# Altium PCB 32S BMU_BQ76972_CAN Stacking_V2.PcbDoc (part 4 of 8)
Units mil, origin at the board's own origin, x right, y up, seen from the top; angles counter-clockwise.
Board outline 7319.29 x 5216.54 mil, 4 copper layers (Top Layer, Layer 1, Layer 2, Bottom Layer), stack 73.068 mil thick; 811 components, 524 nets, 2320 pads, 2669 vias.
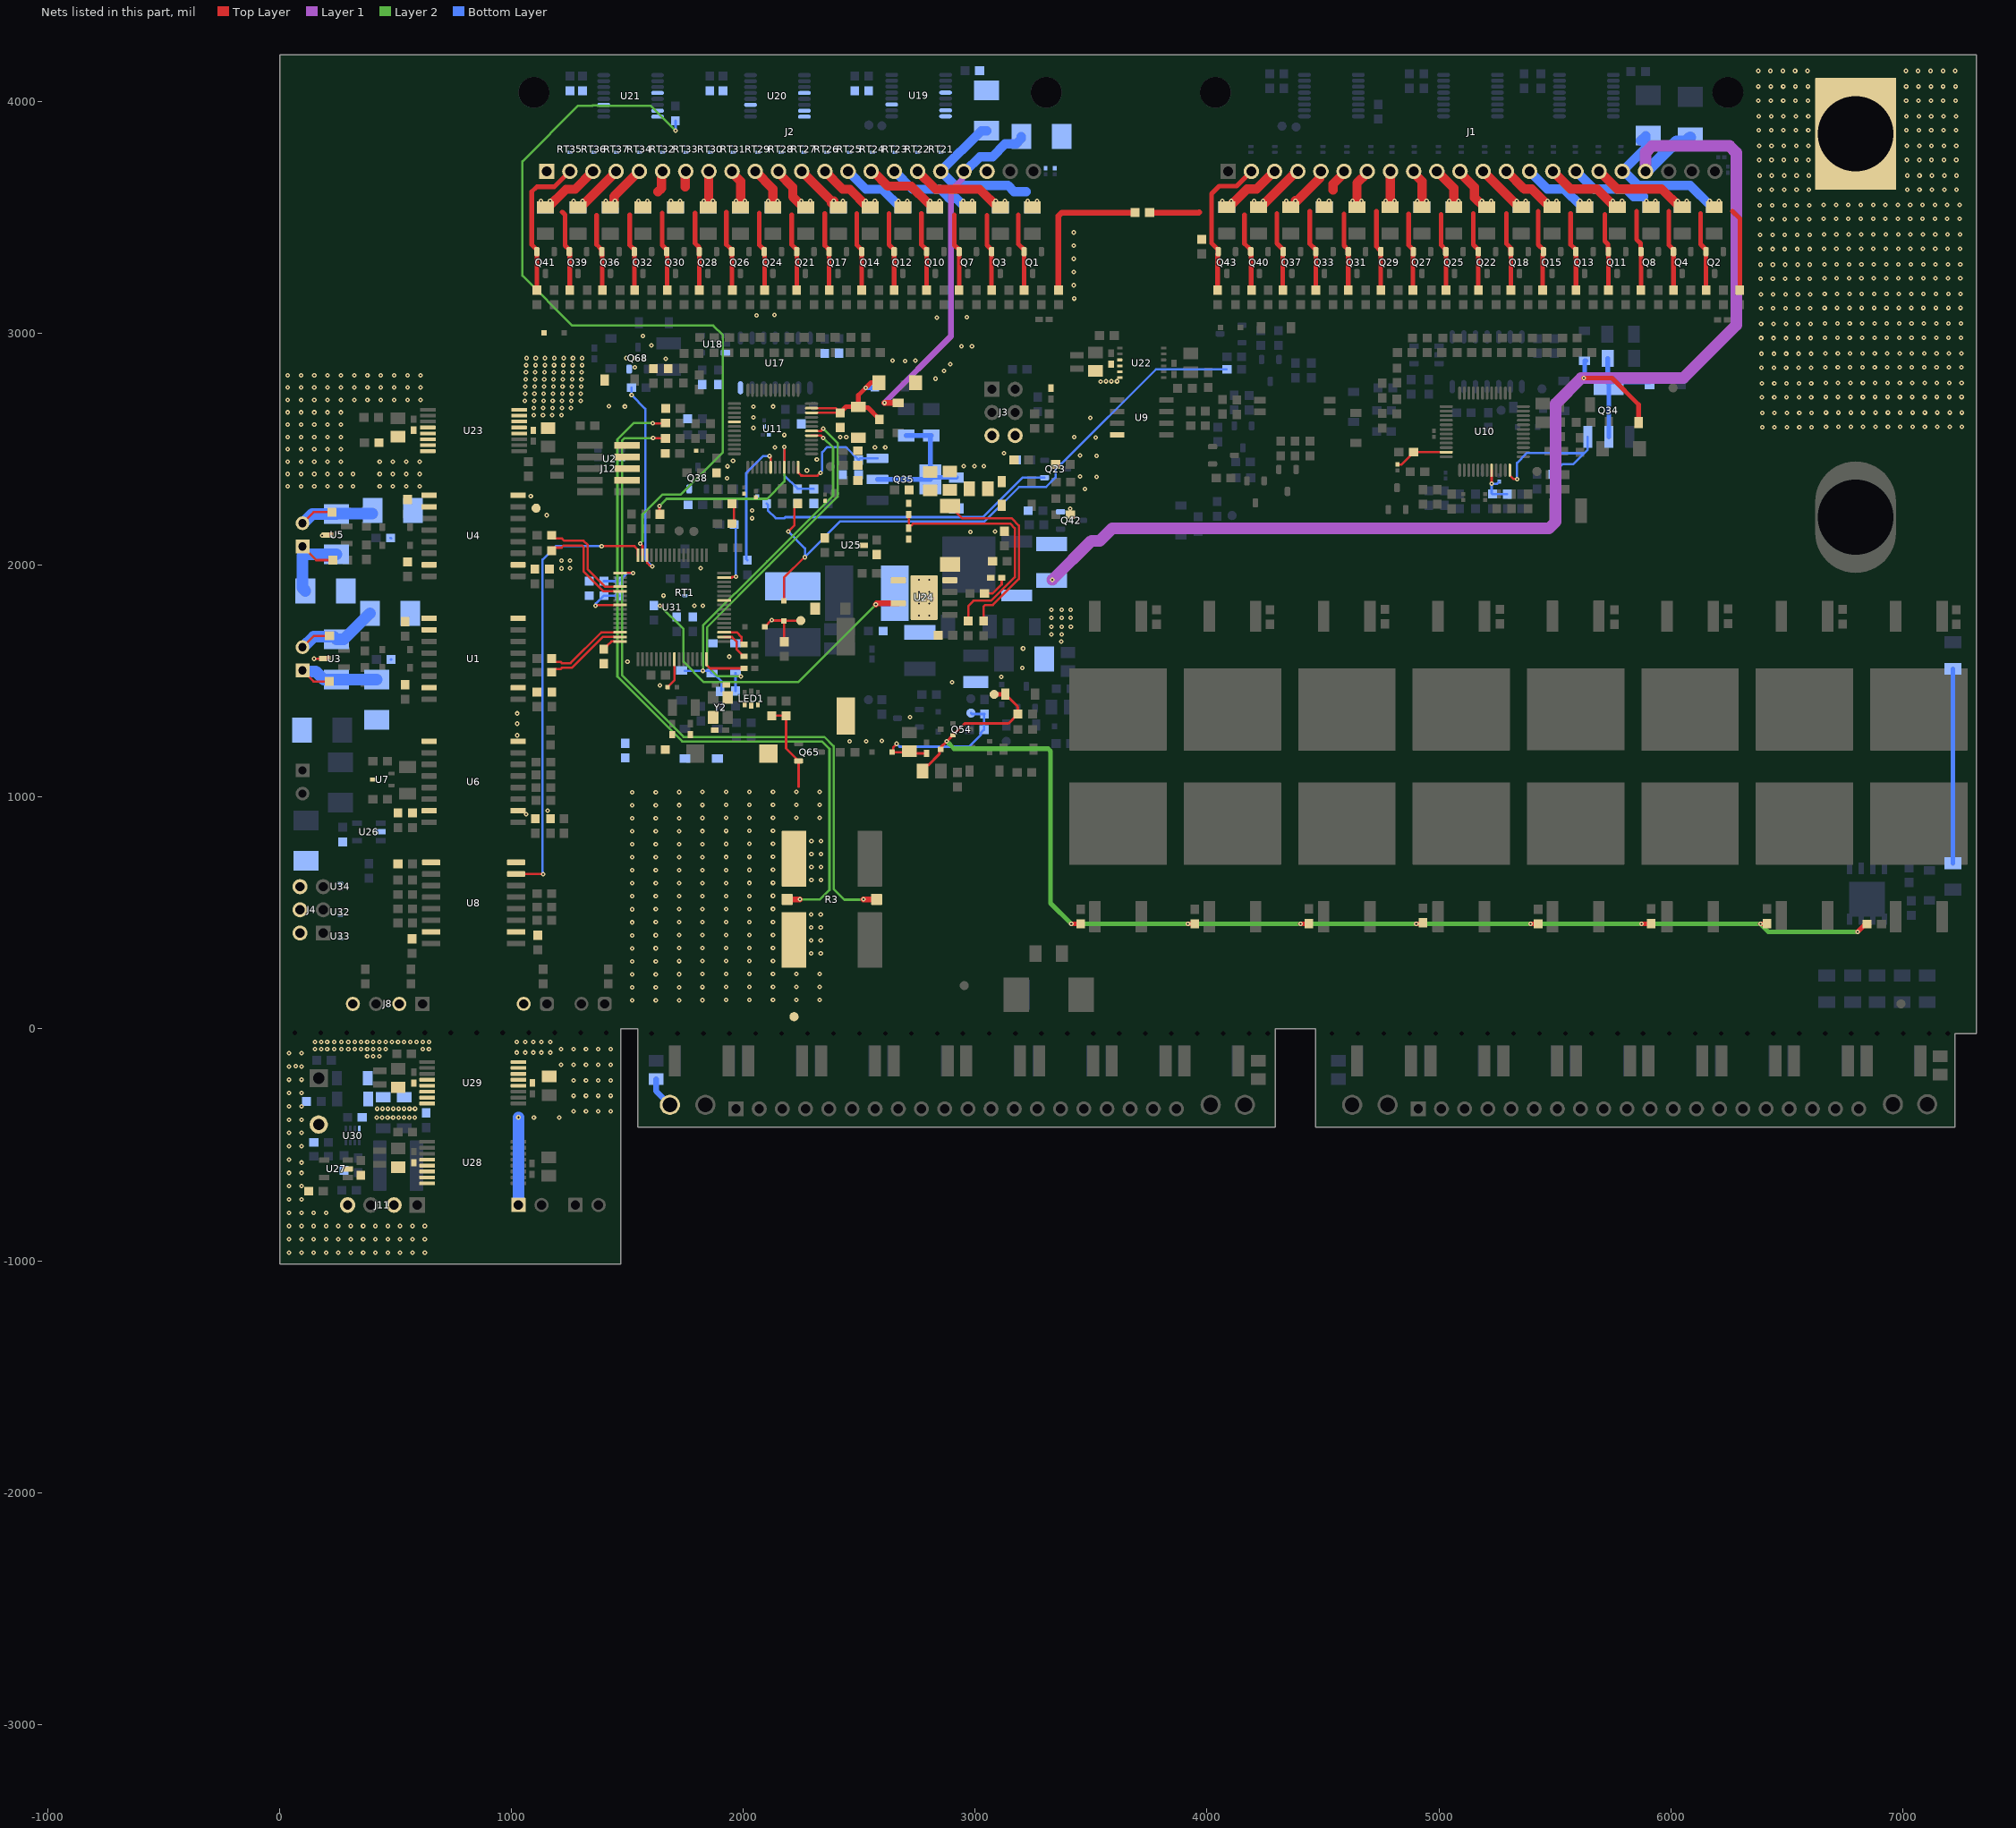
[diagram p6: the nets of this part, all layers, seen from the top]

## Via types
v1: diameter 19.68, hole 7.87, Top Layer to Bottom Layer, tented both sides, 2668 vias
v2: diameter 40, hole 20, Top Layer to Bottom Layer, 1 vias

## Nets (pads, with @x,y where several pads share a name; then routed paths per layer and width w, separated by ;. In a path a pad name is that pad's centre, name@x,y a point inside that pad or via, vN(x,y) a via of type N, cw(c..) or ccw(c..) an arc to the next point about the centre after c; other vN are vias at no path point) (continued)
BAT+: F1.1
  other v1: 6394.6,2596.17 6447.9,2596.17 6501.2,2596.17 6554.5,2596.17 6607.8,2596.17 6670.09,2597.79 6723.39,2597.79 6776.69,2597.79 6829.99,2597.79 6883.29,2597.79 6936.59,2597.79 6989.89,2597.79 7043.19,2597.79 7096.49,2597.79 7149.79,2597.79 7203.09,2597.79 7256.39,2597.79 6394.6,2656.71 6447.9,2656.71 6501.2,2656.71 6554.5,2656.71 6607.8,2656.71 6670.09,2658.33 6723.39,2658.33 6776.69,2658.33 6829.99,2658.33 6883.29,2658.33 6936.59,2658.33 6989.89,2658.33 7043.19,2658.33 7096.49,2658.33 7149.79,2658.33 7203.09,2658.33 7256.39,2658.33 6393.13,2724.21 6446.43,2724.21 6499.73,2724.21 6553.03,2724.21 6606.33,2724.21 6668.62,2725.83 6721.92,2725.83 6775.22,2725.83 6828.52,2725.83 6881.82,2725.83 6935.12,2725.83 6988.42,2725.83 7041.72,2725.83 7095.02,2725.83 7148.32,2725.83 7201.62,2725.83 7254.92,2725.83 6393.13,2784.75 6446.43,2784.75 6499.73,2784.75 6553.03,2784.75 6606.33,2784.75 6668.62,2786.37 6721.92,2786.37 6775.22,2786.37 6828.52,2786.37 6881.82,2786.37 6935.12,2786.37 6988.42,2786.37 7041.72,2786.37 7095.02,2786.37 7148.32,2786.37 7201.62,2786.37 7254.92,2786.37 6391.67,2852.25 6444.97,2852.25 6498.27,2852.25 6551.57,2852.25 6604.87,2852.25 6667.16,2853.87 6720.46,2853.87 6773.76,2853.87 6827.06,2853.87 6880.36,2853.87 6933.66,2853.87 6986.96,2853.87 7040.26,2853.87 7093.56,2853.87 7146.86,2853.87 7200.16,2853.87 7253.46,2853.87 6391.67,2912.79 6444.97,2912.79 6498.27,2912.79 6551.57,2912.79 6604.87,2912.79 6667.16,2914.41 6720.46,2914.41 6773.76,2914.41 6827.06,2914.41 6880.36,2914.41 6933.66,2914.41 6986.96,2914.41 7040.26,2914.41 7093.56,2914.41 7146.86,2914.41 7200.16,2914.41 7253.46,2914.41 6390.2,2980.3 6443.51,2980.3 6496.81,2980.3 6550.11,2980.3 6603.41,2980.3 6665.7,2981.91 6719,2981.91 6772.3,2981.91 6825.6,2981.91 6878.9,2981.91 6932.2,2981.91 6985.5,2981.91 7038.8,2981.91 7092.1,2981.91 7145.4,2981.91 7198.7,2981.91 7252,2981.91 6390.2,3040.83 6443.51,3040.83 6496.81,3040.83 6550.11,3040.83 6603.41,3040.83 6665.7,3042.45 6719,3042.45 6772.3,3042.45 6825.6,3042.45 6878.9,3042.45 6932.2,3042.45 6985.5,3042.45 7038.8,3042.45 7092.1,3042.45 7145.4,3042.45 7198.7,3042.45 7252,3042.45 6388.74,3108.34 6442.04,3108.34 6495.34,3108.34 6548.64,3108.34 6601.94,3108.34 6664.23,3109.95 6717.53,3109.95 6770.83,3109.95 6824.13,3109.95 6877.43,3109.95 6930.73,3109.95 6984.03,3109.95 7037.33,3109.95 7090.63,3109.95 7143.93,3109.95 7197.23,3109.95 7250.53,3109.95 6388.74,3168.88 6442.04,3168.88 6495.34,3168.88 6548.64,3168.88 6601.94,3168.88 6664.23,3170.49 6717.53,3170.49 6770.83,3170.49 6824.13,3170.49 6877.43,3170.49 6930.73,3170.49 6984.03,3170.49 7037.33,3170.49 7090.63,3170.49 7143.93,3170.49 7197.23,3170.49 7250.53,3170.49 6387.28,3236.38 6440.58,3236.38 6493.88,3236.38 6547.18,3236.38 6600.48,3236.38 6662.77,3237.99 6716.07,3237.99 6769.37,3237.99 6822.67,3237.99 6875.97,3237.99 6929.27,3237.99 6982.57,3237.99 7035.87,3237.99 7089.17,3237.99 7142.47,3237.99 7195.77,3237.99 7249.07,3237.99 6387.28,3296.92 6440.58,3296.92 6493.88,3296.92 6547.18,3296.92 6600.48,3296.92 6662.77,3298.53 6716.07,3298.53 6769.37,3298.53 6822.67,3298.53 6875.97,3298.53 6929.27,3298.53 6982.57,3298.53 7035.87,3298.53 7089.17,3298.53 7142.47,3298.53 7195.77,3298.53 7249.07,3298.53 6385.81,3364.42 6439.11,3364.42 6492.41,3364.42 6545.71,3364.42 6599.01,3364.42 6661.31,3366.03 6714.61,3366.03 6767.91,3366.03 6821.21,3366.03 6874.51,3366.03 6927.81,3366.03 6981.11,3366.03 7034.41,3366.03 7087.71,3366.03 7141.01,3366.03 7194.31,3366.03 7247.61,3366.03 6385.81,3424.96 6439.11,3424.96 6492.41,3424.96 6545.71,3424.96 6599.01,3424.96 6661.31,3426.57 6714.61,3426.57 6767.91,3426.57 6821.21,3426.57 6874.51,3426.57 6927.81,3426.57 6981.11,3426.57 7034.41,3426.57 7087.71,3426.57 7141.01,3426.57 7194.31,3426.57 7247.61,3426.57 6384.35,3492.46 6437.65,3492.46 6490.95,3492.46 6544.25,3492.46 6597.55,3492.46 6659.84,3494.07 6713.14,3494.07 6766.44,3494.07 6819.74,3494.07 6873.04,3494.07 6926.34,3494.07 6979.64,3494.07 7032.94,3494.07 7086.24,3494.07 7139.54,3494.07 7192.84,3494.07 7246.14,3494.07 6384.35,3553 6437.65,3553 6490.95,3553 6544.25,3553 6597.55,3553 6659.84,3554.61 6713.14,3554.61 6766.44,3554.61 6819.74,3554.61 6873.04,3554.61 6926.34,3554.61 6979.64,3554.61 7032.94,3554.61 7086.24,3554.61 7139.54,3554.61 7192.84,3554.61 7246.14,3554.61 6382.89,3620.5 6436.19,3620.5 6489.49,3620.5 6542.79,3620.5 6596.09,3620.5 7020.03,3620.5 7073.33,3620.5 7126.63,3620.5 7179.93,3620.5 7233.23,3620.5 6382.89,3681.04 6436.19,3681.04 6489.49,3681.04 6542.79,3681.04 6596.09,3681.04 7020.03,3681.04 7073.33,3681.04 7126.63,3681.04 7179.93,3681.04 7233.23,3681.04 6381.42,3748.54 6434.72,3748.54 6488.02,3748.54 6541.32,3748.54 6594.62,3748.54 7018.56,3748.54 7071.86,3748.54 7125.16,3748.54 7178.46,3748.54 7231.76,3748.54 6381.42,3809.08 6434.72,3809.08 6488.02,3809.08 6541.32,3809.08 6594.62,3809.08 7018.56,3809.08 7071.86,3809.08 7125.16,3809.08 7178.46,3809.08 7231.76,3809.08 6379.96,3876.58 6433.26,3876.58 6486.56,3876.58 6539.86,3876.58 6593.16,3876.58 7017.1,3876.58 7070.4,3876.58 7123.7,3876.58 7177,3876.58 7230.3,3876.58 6379.96,3937.12 6433.26,3937.12 6486.56,3937.12 6539.86,3937.12 6593.16,3937.12 7017.1,3937.12 7070.4,3937.12 7123.7,3937.12 7177,3937.12 7230.3,3937.12 6378.5,4004.62 6431.8,4004.62 6485.1,4004.62 6538.4,4004.62 6591.7,4004.62 7015.64,4004.62 7068.94,4004.62 7122.24,4004.62 7175.54,4004.62 7228.84,4004.62 6378.5,4065.16 6431.8,4065.16 6485.1,4065.16 6538.4,4065.16 6591.7,4065.16 7015.64,4065.16 7068.94,4065.16 7122.24,4065.16 7175.54,4065.16 7228.84,4065.16 6377.03,4132.66 6430.33,4132.66 6483.63,4132.66 6536.93,4132.66 6590.23,4132.66 7014.17,4132.66 7067.47,4132.66 7120.77,4132.66 7174.07,4132.66 7227.37,4132.66
BAT_IN: D10.2 C116.1 D2.2 D43.2 J1.19 R308.1 | length 5641.8
  Top Layer w20: v1(5624.52,2807.47) 5747.27,2807.47 5861.9,2692.85 D10.2@5861.9,2615.29
  Layer 1 w50: v1(3332.48,1937.18) 3501.47,2106.16 3537.95,2106.16 3590.51,2158.73 5474.67,2158.73 5503.96,2188.02 5503.96,2697.09 5614.34,2807.47 v1(5624.52,2807.47) 6054.95,2807.47 6282.83,3035.35 6282.83,3779.79 6253.54,3809.08 5920.57,3809.08 5891.28,3779.79 J1.19@5891.28,3699.61
  Bottom Layer w20: v1(5624.52,2807.47) 5628.49,2811.44 D2.2@5628.49,2881.95 D2.2@5634.49,2881.95
  Bottom Layer w50: J1.19@5891.28,3699.61 5895.75,3699.61 6025.29,3829.14 6066.23,3829.14 D43.2@6083.73,3846.64
BOT_ALERT: R11.1 R227.2 | length 89
  Top Layer w10: R11.1@1951.09,2179.71 1958.92,2187.54 R227.2@1958.92,2265.5
BOT_BAT: C70.2 C76.2 D3.2 D42.1 R198.2 U11.46 U11.47 | length 663.1
  Top Layer w10: U11.46@2293.98,2657.93 C76.2@2417.03,2657.93 ; U11.47@2293.98,2677.61 2398.33,2677.61 C76.2@2417.72,2658.22
  Top Layer w20: C76.2@2417.72,2657.24 2417.72,2658.22 2443.2,2683.71 C70.2@2496.13,2683.71 ; D42.1@2584.56,2787.97 2550.44,2787.97 2496.13,2733.67 C70.2@2496.13,2683.71 ; R198.2@2586.94,2629.57 2586.94,2630.56 2536.99,2680.51 2499.33,2680.51 C70.2@2496.13,2683.71
  Bottom Layer w20: v1(2527.95,2764.85) 2558.08,2764.85 D3.2@2567.64,2774.41
BOT_BAT_IN: D6.2 D45.2 J2.19 | length 1523.3
  Top Layer w25: v1(2608.27,2700.79) D6.2@2667.32,2700.79
  Layer 1 w25: v1(2608.27,2700.79) 2894.7,2987.22 2894.7,3617.24 2943.49,3666.03 2943.49,3691.66 J2.19@2951.43,3699.61
  Bottom Layer w25: J2.19@2945.74,3705.3 J2.19@2951.43,3699.61
  Bottom Layer w40: J2.19@2951.43,3699.61 2957.55,3699.61 3020.44,3762.5 3074.28,3762.5 3129.55,3817.76 3176.55,3817.76 3199.05,3840.26 D45.2@3199.05,3849.61
BOT_CB: R190.1 U31.14 | length 869.7
  Top Layer w10: U31.14@1584.51,2043.51 1585.29,2042.73 1585.29,2009.74 1597.19,1997.84 1605.21,1997.84 v1(1607.07,1995.99)
  Bottom Layer w10: R190.1@1517.6,2766.49 v1(1517.6,2734.26) 1576.61,2675.25 1576.61,2104.46 1577.35,2103.72 1577.35,2084.8 1576.61,2084.06 1576.61,2026.44 v1(1607.07,1995.99)
BOT_DDSG: D1.1 D17.1 R293.1 TP13.1 | length 255.2
  Top Layer w10: D17.1@2092.79,1734.91 2121.18,1763.3 v1(2122.12,1763.3) 2123.6,1761.82 D1.1@2169.28,1761.82 ; R293.1@2176.72,1669.96 2175.2,1671.49 D1.1@2175.2,1760.33 2246.14,1760.33 TP13.1@2247.37,1761.57
  Bottom Layer w10: v1@2120.26,1761.45 v1(2122.12,1763.3)
BOT_INH: R295.1 U31.15 | length 3459.2
  Top Layer w10: v1(1554.51,2094.26) 1564.82,2083.93 U31.15@1564.82,2043.51
  Layer 2 w10: v1(1554.51,2094.26) 1554.51,2094.51 1564.96,2104.96 1564.96,2219.8 1650.01,2304.85 1728.21,2304.85 1911.63,2488.27 1911.63,2992.26 1869.86,3034.04 1261.64,3034.04 1046.8,3248.87 1046.8,3742.12 1287.41,3982.73 1349.84,3982.73 1350.58,3983.47 1369.51,3983.47 1370.25,3982.73 1599.16,3982.73 v1(1706.98,3874.91)
  Bottom Layer w12: v1(1706.98,3874.91) R295.1@1706.98,3917.91
BOT_LD: D19.1 D35.2 R302.1 U11.41 | length 1528.3
  Top Layer w10: U11.41@2293.98,2559.5 2334.84,2559.5 2344.49,2549.85 v1(2345.17,2549.85)
  Layer 2 w10: v1(1825.8,1544.78) 1825.68,1544.91 1825.68,1739.74 2102.39,2016.45 2387.07,2301.13 2387.07,2507.95 v1(2345.17,2549.85)
  Bottom Layer w10: D35.2@1748.2,1544.78 v1(1825.8,1544.78) 1854.22,1544.78 D19.1@1864.34,1534.65 1870.35,1534.65 1905.58,1499.42 R302.1@1905.58,1457.5
BOT_PACK: D20.1 R299.1 U11.42 | length 1578.7
  Top Layer w10: U11.42@2293.98,2579.19 2334.84,2579.19 2344.68,2589.03 v1(2345.17,2589.03)
  Layer 2 w10: v1(1989.59,1520.84) 1889.38,1520.84 1843.68,1566.54 1843.68,1732.28 2109.85,1998.45 2406.99,2295.59 2406.99,2527.22 v1(2345.17,2589.03)
  Bottom Layer w10: R299.1@1966.1,1457.5 D20.1@1966.1,1534.65
BOT_SHUT: C84.1 R15.1 R252.2 U11.33 | length 1129.3
  Top Layer w10: v1(1637.97,2256.18) 1637.97,2222.81 R15.1@1640.28,2220.5 ; U11.33@2176.85,2422.69 v1@2176.85,2509.85
  Layer 2 w10: v1(1637.97,2256.18) 1668.6,2286.8 2102.41,2286.8 2176.85,2361.24 v1(2176.85,2510.13)
  Bottom Layer w10: v1(2176.85,2510.13) 2176.85,2387.3 2233.63,2330.52 R252.2@2233.63,2329.54 C84.1@2303.73,2329.54
BOT_WAKE: R254.1 U31.63 | length 279.9
  Top Layer w10: U31.63@1917.19,1947.05 1950.18,1947.05 1953.35,1950.23 v1(1967.62,1950.23)
  Bottom Layer w10: R254.1@1960.33,2175.36 1967.62,2168.07 v1(1967.62,1950.23)
BOTAFE_DCHG: Q23.1 R223.2 | length 1311
  Bottom Layer w10: R223.2@2100.42,2265.88 2105.67,2260.63 2105.67,2237.06 2139.59,2203.14 2176.47,2203.14 2180.82,2207.5 3033.14,2207.5 3203.6,2377.95 Q23.1@3299.21,2377.95
BOTAFE_DDSG: D1.2 R222.2 R246.1 | length 2681.6
  Top Layer w10: D1.2@2175.2,1846.95 2175.2,1946.14 2263.89,2034.84 v1(2265.6,2034.84) ; v1(2193.54,2145.41) 2220.49,2172.35 2220.49,2252.84 R222.2@2234.19,2266.55
  Bottom Layer w10: v1(2193.54,2145.41) 2265.6,2073.35 v1(2265.6,2034.84) 2265.6,2036.54 2418.55,2189.5 3040.6,2189.5 3188.95,2337.85 3305.53,2337.85 3346.46,2378.78 3346.46,2414.53 3372.09,2440.17 3374.17,2440.17 3779.4,2845.39 R246.1@4084.81,2845.39
BOTGND_Sim: R365.2 TP28.1 | length 134.8
  Bottom Layer w25: R365.2@1624.02,-217.03 1624.02,-268.3 TP28.1@1683.07,-327.35
BOTHOFF: R18.1 U11.30 | length 559.7
  Top Layer w10: v1(2112.97,2471.17) 2112.97,2468.55 2117.45,2464.07 2117.45,2423.04 U11.30@2117.79,2422.69
  Bottom Layer w10: R18.1@2017.58,2021.75 2012.43,2026.9 2012.43,2397.95 2085.66,2471.17 v1(2112.97,2471.17)
CAN0_RXD: R7.1 U31.31 | length 358.3
  Top Layer w10: R7.1@1173.34,1538.44 1187.04,1552.14 1210.97,1552.14 1216.96,1558.12 1260.68,1558.12 1393.7,1691.15 U31.31@1468.37,1691.15
CAN0_TXD: R6.1 U31.30 | length 358.3
  Top Layer w10: R6.1@1173.34,1597.49 1187.04,1583.79 1210.97,1583.79 1216.96,1577.81 1254.91,1577.81 1386.25,1709.15 1386.43,1709.15 1388.11,1710.83 U31.30@1468.37,1710.83
CAN0H: D51.1 D53.2 L3.2 P3.1 | length 472.6
  Top Layer w10: P3.1@98.53,1546.71 146.17,1499.07 L3.2@214.21,1499.07
  Bottom Layer w50: P3.1@98.53,1546.71 103.06,1542.18 155.12,1542.18 190.75,1506.55 D51.1@244.74,1506.55 418.74,1506.55 D53.2@419.01,1506.82
CAN0L: D51.2 D56.2 L4.2 P3.2 | length 496.6
  Top Layer w10: P3.2@98.53,1646.71 147.75,1695.92 L4.2@214.68,1695.92
  Bottom Layer w50: P3.2@98.53,1646.71 100.98,1646.71 146.18,1691.91 233.4,1691.91 D51.2@244.74,1680.56 276.64,1680.56 D56.2@388.72,1792.65
CAN1_RXD: R16.1 U31.21 | length 439.8
  Top Layer w10: R16.1@1175.94,2075.76 1176.4,2076.22 1215.77,2076.22 1225.16,2085.61 1305.01,2085.61 1310.87,2079.75 1310.87,1974.88 1397.75,1888 U31.21@1468.37,1888
CAN1_TXD: R14.1 U31.20 | length 443.9
  Top Layer w10: R14.1@1175.94,2124.98 1185.63,2115.29 1217.54,2115.29 1226.93,2105.9 1310.17,2105.9 1328.87,2087.2 1328.87,1982.34 1403.52,1907.68 U31.20@1468.37,1907.68
CAN1H: D50.1 D54.2 L6.2 P2.1 | length 461.3
  Top Layer w10: P2.1@98.53,2081.46 157.59,2022.4 L6.2@229.46,2022.4
  Bottom Layer w50: D54.2@110.69,1889.76 98.53,1901.92 98.53,2041.93 104.46,2047.86 D50.1@244.74,2047.86
CAN1L: D50.2 D57.2 L7.2 P2.2 | length 466
  Top Layer w10: P2.2@98.53,2181.46 146.17,2229.09 L7.2@226.02,2229.09
  Bottom Layer w50: P2.2@98.53,2181.46 100.98,2181.46 141.4,2221.87 D50.2@244.74,2221.87 246.27,2223.4 D57.2@399.96,2223.4
Cell0: J2.2 Q41.2 R185.1 | length 634.6
  Top Layer w20: R185.1@1109.14,3186.81 Q41.2@1109.14,3353.15 1107.33,3354.96 1107.33,3362.83 1087.02,3383.15 1087.02,3611.3 1108.8,3633.09 1184.91,3633.09 J2.2@1251.43,3699.61
Cell1: J2.3 Q39.2 R149.1 R151.1 R181.1 | length 621.7
  Top Layer w20: 1216.81,3523.62 1219.11,3523.62 1230.83,3511.91 1230.83,3379.45 1249.25,3361.02 Q39.2@1249.25,3353.15 1249.25,3345.28 1251.22,3343.31 R181.1@1251.22,3186.81
  Top Layer w40: R149.1@1146.54,3544.09 1157.37,3544.09 1235.38,3622.11 1273.93,3622.11 J2.3@1351.43,3699.61
  other v1: 1126.86,3571.65 1166.23,3571.65
Cell2: J2.4 Q36.2 R144.1 R146.1 R177.1 | length 563.2
  Top Layer w20: 1366.68,3509.55 1366.68,3383.7 1387.55,3362.83 1387.55,3354.96 1390.53,3351.98 1390.53,3187.98 R177.1@1391.7,3186.81
  Top Layer w40: R144.1@1286.65,3544.09 1297.48,3544.09 1451.43,3698.05 J2.4@1451.43,3699.61
  other v1: 1266.97,3571.65 1306.34,3571.65
Cell3: J2.5 Q32.2 R140.1 R142.1 R173.1 | length 547.7
  Top Layer w20: 1510.06,3511.91 1510.06,3380.43 1529.47,3361.02 Q32.2@1529.47,3353.15 1530.45,3352.17 1530.45,3187.79 R173.1@1531.44,3186.81
  Top Layer w40: R140.1@1426.48,3544.09 1437.18,3544.09 1442.77,3549.69 1442.77,3591.34 1551.04,3699.61 J2.5@1551.43,3699.61
  other v1: 1406.79,3571.65 1446.16,3571.65
Cell4: J2.6 Q30.2 R136.1 R138.1 R169.1 | length 438.9
  Top Layer w20: 1649.85,3519.71 1649.85,3380.75 1669.58,3361.02 Q30.2@1669.58,3353.15 1669.58,3345.28 1671.54,3343.31 R169.1@1671.54,3186.81
  Top Layer w40: 1631.34,3610.91 1646.36,3625.92 1646.36,3694.53 J2.6@1651.43,3699.61
  other v1: 1547.18,3571.65 1586.55,3571.65
Cell5: J2.7 Q28.2 R132.1 R134.1 R165.1 | length 415.3
  Top Layer w20: 1791.75,3520.22 1791.75,3388.78 1807.87,3372.66 1807.87,3354.96 Q28.2@1809.68,3353.15 R165.1@1809.68,3186.81
  Top Layer w40: 1749.7,3633.09 1749.7,3697.87 J2.7@1751.43,3699.61 J2.7@1751.43,3692.43
  other v1: 1687.29,3571.65 1726.66,3571.65
Cell6: J2.8 Q26.2 R128.1 R130.1 R161.1 | length 503.9
  Top Layer w20: 1926.9,3523.62 1926.9,3383.92 1949.79,3361.02 Q26.2@1949.79,3353.15 1951.08,3351.86 1951.08,3188.1 R161.1@1952.37,3186.81
  Top Layer w40: R128.1@1849.05,3544.09 1850.24,3545.28 1850.24,3698.42 J2.8@1851.43,3699.61
  other v1: 1829.37,3571.65 1868.74,3571.65
Cell7: J2.9 Q24.2 R124.1 R126.1 R157.1 | length 512.9
  Top Layer w20: 2069.01,3519.71 2069.01,3381.91 2089.9,3361.02 Q24.2@2089.9,3353.15 2089.9,3345.28 2091.87,3343.31 R157.1@2091.87,3186.81
  Top Layer w40: J2.9@1951.43,3699.61 1951.43,3692.43 1987.8,3656.06 R124.1@1987.8,3544.09
  other v1: 1968.11,3571.65 2007.48,3571.65
Cell8: J2.10 Q21.2 R119.1 R120.1 R122.1 | length 521.1
  Top Layer w20: 2208.21,3511.91 2208.21,3382.82 2230.01,3361.02 Q21.2@2230.01,3353.15 R119.1@2230.01,3186.81
  Top Layer w40: J2.10@2051.43,3699.61 2127.3,3623.74 R120.1@2127.3,3544.09
  other v1: 2107.62,3571.65 2146.99,3571.65
Cell9: J2.11 Q17.2 R83.1 R85.1 R115.1 | length 548.4
  Top Layer w20: 2351.43,3516.73 2351.43,3379.71 2370.12,3361.02 Q17.2@2370.12,3353.15 R115.1@2370.12,3186.81
  Top Layer w40: J2.11@2151.43,3699.61 2151.43,3692.43 2213.08,3630.78 2213.08,3589.56 2258.55,3544.09 R83.1@2269.38,3544.09
  other v1: 2249.69,3571.65 2289.06,3571.65
Cell10: J2.12 Q14.2 R79.1 R81.1 R111.1 | length 568
  Top Layer w20: 2489.34,3518.23 2489.34,3381.91 2508.41,3362.83 2508.41,3354.96 Q14.2@2510.22,3353.15 R111.1@2510.22,3186.81
  Top Layer w40: J2.12@2251.43,3699.61 2379.39,3571.65 v1(2389.8,3571.65) ; R79.1@2380.45,3562.3 2398.66,3544.09 R79.1@2409.49,3544.09
  other v1: 2429.17,3571.65
Cell11: J2.13 Q12.2 R75.1 R77.1 R107.1 | length 599.7
  Top Layer w20: 2628.21,3516.73 2628.21,3383.15 2650.33,3361.02 Q12.2@2650.33,3353.15 R107.1@2650.33,3186.81
  Top Layer w40: J2.13@2351.43,3699.61 2428.93,3622.11 2458.8,3622.11 2536.81,3544.09 R75.1@2547.64,3544.09
  other v1: 2527.95,3571.65 2567.32,3571.65
Cell12: J2.14 Q10.2 R71.1 R73.1 R103.1 | length 650.9
  Top Layer w20: 2768.32,3516.73 2768.32,3383.15 2790.44,3361.02 Q10.2@2790.44,3353.15 R103.1@2790.44,3186.81
  Top Layer w30: R71.1@2677.14,3544.09 R71.1@2687.97,3544.09
  Bottom Layer w40: J2.14@2451.43,3699.61 2528.93,3622.11 2599.13,3622.11 2677.14,3544.09 R73.1@2687.97,3544.09
  other v1: 2668.28,3571.65 2707.65,3571.65
Cell13: J2.15 Q7.2 R68.1 R70.1 R99.1 | length 672.4
  Top Layer w20: 2910.16,3511.91 2910.16,3381.42 2930.55,3361.02 Q7.2@2930.55,3353.15 R99.1@2930.55,3186.81
  Top Layer w40: J2.15@2551.43,3699.61 2558.61,3699.61 2622.78,3635.44 2723.72,3635.44 2796.85,3562.3 2815.06,3544.09 R68.1@2825.89,3544.09
  other v1: 2806.2,3571.65 2845.57,3571.65
Cell14: J2.16 Q3.2 R63.1 R65.1 R95.1 | length 711.9
  Top Layer w20: 3050.81,3509.49 3050.81,3380.87 3070.66,3361.02 Q3.2@3070.66,3353.15 R95.1@3070.66,3186.81
  Bottom Layer w40: J2.16@2651.43,3699.61 2728.93,3622.11 2849.3,3622.11 2873.72,3597.69 2873.9,3597.69 2888.57,3583.01 2888.57,3582.83 2918.38,3582.83 2957.12,3544.09 R65.1@2967.95,3544.09
  other v1: 2948.26,3571.65 2987.63,3571.65
Cell15: J2.17 Q1.2 R59.1 R61.1 R91.1 | length 756.6
  Top Layer w20: 3186.11,3511.91 3186.11,3385.68 3210.76,3361.02 Q1.2@3210.76,3353.15 3211.02,3352.89 3211.02,3187.07 R91.1@3211.28,3186.81
  Top Layer w40: J2.17@2751.43,3699.61 2828.93,3622.11 3019.22,3622.11 3097.23,3544.09 R59.1@3108.06,3544.09
  other v1: 3088.37,3571.65 3127.74,3571.65
Cell16: D46.2 J2.18 R55.1 R57.1 R87.1 R152.1 | length 1342
  Top Layer w25: R87.1@3359.26,3186.81 3359.26,3507.01 3373.9,3521.66 R152.1@3688.98,3521.66
  Bottom Layer w40: D46.2@3049.1,3874.41 3026.24,3874.41 J2.18@2851.43,3699.61 2912.7,3638.34 3076.81,3638.34 3141.65,3638.34 3167.85,3612.13 3220.36,3612.13 ; R57.1@3235.89,3544.09 R57.1@3246.72,3544.09
  other v1: 3227.03,3571.65 3266.4,3571.65
Cell16B: J1.2 Q43.2 R152.2 R153.1 R186.1 | length 854.3
  Top Layer w20: R186.1@4045.79,3186.81 4045.79,3342.87 4048.2,3345.28 Q43.2@4048.2,3353.15 4046.39,3354.96 4046.39,3362.83 4019.76,3389.46 4019.76,3602.73 4052.47,3635.44 4127.11,3635.44 J1.2@4191.28,3699.61
  Top Layer w25: R152.2@3751.97,3521.66 3964.81,3521.66 3965.63,3522.48
Cell17: J1.3 Q40.2 R148.1 R150.1 R182.1 | length 607.8
  Top Layer w20: 4161.65,3511.91 4161.65,3387.83 4188.46,3361.02 Q40.2@4188.46,3353.15 4190.27,3351.34 4190.27,3188.68 R182.1@4192.14,3186.81
  Top Layer w40: R148.1@4085.18,3545.08 4096.01,3545.08 4173.53,3622.6 4214.27,3622.6 J1.3@4291.28,3699.61
  other v1: 4065.5,3572.64 4104.87,3572.64
Cell18: J1.4 Q37.2 R145.1 R147.1 R178.1 | length 575.2
  Top Layer w20: 4301.63,3516.73 4301.63,3388.12 4328.72,3361.02 Q37.2@4328.72,3353.15 4328.72,3345.28 4326.82,3343.38 R178.1@4326.82,3186.81
  Top Layer w40: R145.1@4222.01,3545.08 4232.83,3545.08 4387.36,3699.61 J1.4@4391.28,3699.61
  other v1: 4202.32,3572.64 4241.69,3572.64
Cell19: J1.5 Q33.2 R141.1 R143.1 R174.1 | length 547.1
  Top Layer w20: 4442.9,3527.56 4442.9,3387.1 4468.98,3361.02 Q33.2@4468.98,3353.15 R174.1@4468.98,3186.81
  Top Layer w40: R141.1@4361.64,3545.08 R141.1@4372.47,3545.08 ; v1(4381.33,3572.64) 4389.87,3572.64 4486.2,3668.97 4486.2,3694.53 J1.5@4491.28,3699.61 J1.5@4491.28,3692.43
  other v1: 4341.96,3572.64
Cell20: J1.6 Q31.2 R137.1 R139.1 R170.1 | length 437
  Top Layer w20: 4591.28,3516.24 4591.28,3378.99 4607.44,3362.83 4607.44,3354.96 Q31.2@4609.25,3353.15 R170.1@4609.25,3186.81
  Top Layer w40: 4543.79,3619.11 4543.79,3644.94 4591.28,3692.43 J1.6@4591.28,3699.61
  other v1: 4526.07,3572.64 4483.34,3573.46
Cell21: J1.7 Q29.2 R133.1 R135.1 R166.1 | length 599.8
  Top Layer w20: 4730.71,3527.56 4730.71,3374.55 4742.42,3362.83 4747.7,3362.83 4749.51,3361.02 R166.1@4749.51,3186.81
  Top Layer w40: R133.1@4646.65,3545.08 4646.65,3647.8 ; 4646.65,3572.64 4646.65,3647.8 ; J1.7@4691.28,3699.61 4691.28,3692.43 4646.65,3647.8
  other v1: 4626.96,3572.64 4666.33,3572.64
Cell22: J1.8 Q27.2 R129.1 R131.1 R162.1 | length 493.4
  Top Layer w20: 4869.99,3515.94 4869.99,3380.81 4887.96,3362.83 4887.96,3354.96 Q27.2@4889.77,3353.15 4889.77,3345.28 4887.68,3343.19 R162.1@4887.68,3186.81
  Top Layer w40: R129.1@4789.56,3545.08 4790.42,3545.94 4790.42,3698.75 J1.8@4791.28,3699.61
  other v1: 4769.88,3572.64 4809.25,3572.64
Cell23: J1.9 Q25.2 R125.1 R127.1 R158.1 | length 505.6
  Top Layer w20: 5009.04,3514.1 5009.04,3382.02 5028.22,3362.83 5028.22,3354.96 5030.28,3352.9 5030.28,3187.06 R158.1@5030.53,3186.81
  Top Layer w40: J1.9@4891.28,3699.61 4891.28,3692.43 4927.17,3656.53 R125.1@4927.17,3545.08
  other v1: 4907.49,3572.64 4946.86,3572.64
Cell24: J1.10 Q22.2 R121.1 R123.1 R154.1 | length 523.7
  Top Layer w20: 5148.8,3516.73 5148.8,3382.52 5170.3,3361.02 Q22.2@5170.3,3353.15 R154.1@5170.3,3186.81
  Top Layer w40: J1.10@4991.28,3699.61 5064.55,3626.34 R121.1@5064.55,3545.08
  other v1: 5044.86,3572.64 5084.23,3572.64
Cell25: J1.11 Q18.2 R84.1 R86.1 R116.1 | length 546.2
  Top Layer w20: 5291.28,3516.73 5291.28,3387.71 5308.75,3370.24 5308.75,3354.96 Q18.2@5310.56,3353.15 R116.1@5310.56,3186.81
  Top Layer w40: J1.11@5091.28,3699.61 5091.28,3692.43 5152.92,3630.78 5152.92,3587.06 5194.9,3545.08 R84.1@5205.73,3545.08
  other v1: 5186.04,3572.64 5225.41,3572.64
Cell26: J1.12 Q15.2 R80.1 R82.1 R112.1 | length 580
  Top Layer w20: 5428.71,3527.56 5428.71,3383.13 5450.82,3361.02 Q15.2@5450.82,3353.15 5450.82,3345.28 5447.66,3342.11 R112.1@5447.66,3186.81
  Top Layer w40: J1.12@5191.28,3699.61 5191.28,3698.24 5344.43,3545.08 R80.1@5355.26,3545.08
  other v1: 5335.58,3572.64 5374.95,3572.64
Cell27: J1.13 Q13.2 R76.1 R78.1 R108.1 | length 600.3
  Top Layer w20: 5568.28,3516.73 5568.28,3383.82 5591.08,3361.02 Q13.2@5591.08,3353.15 R108.1@5591.08,3186.81
  Top Layer w40: J1.13@5291.28,3699.61 5368.28,3622.6 5399.88,3622.6 5477.4,3545.08 R76.1@5488.22,3545.08
  other v1: 5468.54,3572.64 5507.91,3572.64
Cell28: J1.14 Q11.2 R72.1 R74.1 R104.1 | length 634.6
  Top Layer w20: 5716.05,3513.89 5716.05,3397.86 5729.54,3384.37 5729.54,3354.96 Q11.2@5731.35,3353.15 R104.1@5731.35,3186.81
  Bottom Layer w40: J1.14@5391.28,3699.61 5468.28,3622.6 5540.14,3622.6 5617.66,3545.08 R74.1@5628.49,3545.08
  other v1: 5608.8,3572.64 5648.17,3572.64
Cell29: J1.15 Q8.2 R67.1 R69.1 R100.1 | length 691.8
  Top Layer w20: 5852.76,3527.56 5852.76,3405.39 5869.8,3388.35 5869.8,3354.96 Q8.2@5871.61,3353.15 R100.1@5871.61,3186.81
  Top Layer w40: J1.15@5491.28,3699.61 5568.28,3622.6 5682.12,3622.6 5759.64,3545.08 R67.1@5770.47,3545.08
  other v1: 5750.78,3572.64 5790.15,3572.64
Cell30: J1.16 Q4.2 R64.1 R66.1 R96.1 | length 697.6
  Top Layer w20: 5991.28,3527.56 5991.28,3381.62 6011.87,3361.02 Q4.2@6011.87,3353.15 6012.19,3352.83 6012.19,3187.13 R96.1@6012.51,3186.81
  Bottom Layer w40: J1.16@5591.28,3699.61 5668.28,3622.6 5807.58,3622.6 5839.84,3590.34 5883.26,3590.34 ; R66.1@5903.88,3545.08 R66.1@5914.71,3545.08
  other v1: 5895.02,3572.64 5934.39,3572.64
Cell31: J1.17 Q2.2 R60.1 R62.1 R92.1 | length 761.9
  Top Layer w20: 6128.35,3516.73 6128.35,3384.81 6152.13,3361.02 Q2.2@6152.13,3353.15 6152.32,3352.96 6152.32,3187 R92.1@6152.51,3186.81
  Top Layer w40: J1.17@5691.28,3699.61 5768.28,3622.6 5960.93,3622.6 6038.45,3545.08 R60.1@6049.27,3545.08
  other v1: 6029.59,3572.64 6068.96,3572.64
Cell32: D44.2 J1.18 R56.1 R58.1 R88.1 | length 1042.5
  Top Layer w20: 6266.14,3527.56 6298.25,3495.45 R88.1@6298.25,3186.81
  Bottom Layer w40: D44.2@5869.88,3831.05 5892.38,3853.55 5892.38,3800.71 J1.18@5791.28,3699.61 5798.46,3699.61 5859.72,3638.34 6016.65,3638.34 6016.78,3638.46 6083.73,3638.46 6177.12,3545.08 R58.1@6187.94,3545.08
  other v1: 6168.26,3572.64 6207.63,3572.64
CSN: R3.4 R251.1 | length 3063.5
  Top Layer w10: v1(1610.27,2548.45) R251.1@1662.86,2548.45
  Top Layer w25: v1(2517.69,558.8) R3.4@2574.8,558.8
  Layer 2 w10: v1(1610.27,2548.45) 1487.22,2548.45 1476.38,2537.6 1476.38,1525.59 1742.13,1259.84 2349.25,1259.84 2389.47,1219.61 2389.47,604.11 2436.03,557.55 2516.44,557.55 v1(2517.69,558.8)
CSP: R3.3 R239.1 | length 3110.9
  Top Layer w10: v1(1609.07,2612.35) R239.1@1662.9,2612.35
  Top Layer w25: R3.3@2188.98,558.8 v1(2244.09,558.8)
  Layer 2 w10: v1(1609.07,2612.35) 1608.07,2613.35 1526.67,2613.35 1456.69,2543.37 1456.69,1519.82 1736.36,1240.16 2339.52,1240.16 2371.47,1208.2 2371.47,599.82 2330.45,558.8 v1(2244.09,558.8)
Current+: C137.2 D32.2 D33.2 Q65.2 R2.2 R3.1 R294.1 TP14.1 | length 390
  Top Layer w10: R294.1@2122.27,1351.24 C137.2@2184.22,1351.24 2184.22,1210.43 Q65.2@2238.2,1156.45 2238.2,1045.53
  other v1: 1520.68,123.39 1621.81,123.69 1722.95,123.98 1824.08,124.27 1925.21,124.56 2026.34,124.86 2127.47,125.15 2228.61,125.44 2329.74,125.73 1520.68,179.5 1621.81,179.79 1722.95,180.08 1824.08,180.38 1925.21,180.67 2026.34,180.96 2127.47,181.25 2228.61,181.55 2329.74,181.84 1520.68,235.6 1621.81,235.9 1722.95,236.19 1824.08,236.48 1925.21,236.77 2026.34,237.07 2127.47,237.36 2228.61,237.65 2329.74,237.95 1520.68,291.71 1621.81,292 1722.95,292.29 1824.08,292.59 1925.21,292.88 2026.34,293.17 2127.47,293.47 2292.59,325.43 2333.9,325.43 1520.68,347.81 1621.81,348.11 1722.95,348.4 1824.08,348.69 1925.21,348.99 2026.34,349.28 2127.47,349.57 2292.59,381.53 2333.9,381.53 1520.68,403.92 1621.81,404.21 1722.95,404.51 1824.08,404.8 1925.21,405.09 2026.34,405.38 2127.47,405.68 2292.59,437.64 2333.9,437.64 1520.68,460.03 1621.81,460.32 1722.95,460.61 1824.08,460.9 1925.21,461.2 2026.34,461.49 2127.47,461.78 2292.59,493.75 2333.9,493.75 1520.68,516.13 1621.81,516.42 1722.95,516.72 1824.08,517.01 1925.21,517.3 2026.34,517.59 2127.47,517.89 1520.68,572.24 1621.81,572.53 1722.95,572.82 1824.08,573.11 1925.21,573.41 2026.34,573.7 2127.47,573.99 1520.68,628.34 1621.81,628.63 1722.95,628.93 1824.08,629.22 1925.21,629.51 2026.34,629.81 2127.47,630.1 2293.31,642.05 2334.62,642.05 1520.68,684.45 1621.81,684.74 1722.95,685.03 1824.08,685.33 1925.21,685.62 2026.34,685.91 2127.47,686.2 2293.31,698.16 2334.62,698.16 1520.68,740.55 1621.81,740.85 1722.95,741.14 1824.08,741.43 1925.21,741.72 2026.34,742.02 2127.47,742.31 2293.31,754.26 2334.62,754.26 1520.68,796.66 1621.81,796.95 1722.95,797.24 1824.08,797.54 1925.21,797.83 2026.34,798.12 2127.47,798.41 2293.31,810.37 2334.62,810.37 1520.68,852.76 1621.81,853.06 1722.95,853.35 1824.08,853.64 1925.21,853.93 2026.34,854.23 2127.47,854.52 1520.68,908.87 1621.81,909.16 1722.95,909.45 1824.08,909.75 1925.21,910.04 2026.34,910.33 2127.47,910.63 2228.61,910.92 2329.74,911.21 1520.68,964.98 1621.81,965.27 1722.95,965.56 1824.08,965.85 1925.21,966.15 2026.34,966.44 2127.47,966.73 2228.61,967.02 2329.74,967.32 1520.68,1021.08 1621.81,1021.37 1722.95,1021.67 1824.08,1021.96 1925.21,1022.25 2026.34,1022.54 2127.47,1022.84 2228.61,1023.13 2329.74,1023.42
Dri_Test: D28.2 D31.2 R272.1 R273.1 R275.1 TP11.1 | length 745.6
  Top Layer w10: v1(2661.62,1230.12) 2645.96,1214.46 2645.96,1198.07 D31.2@2641.73,1193.85 2711.94,1193.85 R272.1@2716.46,1198.36 2726.04,1188.77 D28.2@2790.56,1188.77
  Bottom Layer w10: v1(2661.62,1230.12) 2674.07,1217.67 2973.3,1217.67 3023.68,1268.04 3023.68,1277.08 3037.38,1290.78 R273.1@3038.36,1290.78 3038.36,1356.34 R275.1@3040.45,1358.43 2986.07,1358.43 TP11.1@2981.8,1362.7
DSG_gate: D23.1 D25.1 Q54.2 R255.1 R269.2 R276.2 R280.2 R288.2 R290.2 R304.1 R312.2 R314.2 R321.2 TP30.1 | length 5626.9
  Top Layer w12: R255.1@2772.37,1112.44 2772.37,1118.94 2791.37,1137.94 2797.87,1137.94 2845.9,1185.97 2845.9,1200.59 D25.1@2851.13,1205.82 2851.13,1214.18 v1(2877.46,1240.51) Q54.2@2903.79,1266.84 2955.09,1318.14 3143.97,1318.14 R304.1@3184.09,1358.27 3184.09,1389.88 D23.1@3129.83,1444.14
  Top Layer w20: TP30.1@3081.52,1443.11 3128.8,1443.11 D23.1@3129.83,1444.14 ; v1(3414.54,452.83) R314.2@3444.88,452.83 ; v1(3918.15,452.83) R288.2@3946.85,452.83 ; v1(4402.94,452.83) 4437.17,452.83 R321.2@4438.98,454.65 ; v1(4902.4,452.83) 4926.1,452.83 R312.2@4931.1,457.83 ; v1(5395.94,452.83) R290.2@5428.59,452.83 ; v1(5874.2,452.83) 5913.54,452.83 R269.2@5915.35,454.65 ; v1(6386.7,452.83) 6413.59,452.83 R276.2@6415.4,454.65 ; v1(6806.08,418.31) 6840.61,452.83 R280.2@6846.59,452.83
  Layer 2 w20: v1(2877.46,1240.51) 2909.02,1208.94 3314.54,1208.94 3325.09,1198.4 3325.09,542.28 v1(3414.54,452.83) v1(3918.15,452.83) v1(4402.94,452.83) v1(4902.4,452.83) v1(5395.94,452.83) v1(5874.2,452.83) v1(6386.7,452.83) 6421.23,418.31 v1(6806.08,418.31)
EN: R19.1 U24.3 | length 1387.8
  Top Layer w25: v1(2571.25,1830.87) 2575.79,1835.41 U24.3@2668.39,1835.41
  Layer 2 w10: v1(1640.28,1826.2) 1742.13,1724.36 1742.13,1583.73 1829.79,1496.06 2236.45,1496.06 v1(2571.25,1830.87)
GND: C1.2 C2.2 C3.2 C6.2 C12.1 C14.2 C15.1 C16.2 C19.1 C24.2 C25.1 C26.2 C58.2 C59.2 C60.2 C68.2 C70.1 C71.2 C72.2 C76.1 C77.1 C79.2 C80.1 C81.1 C83.2 C84.2 C87.2 C100.2 C101.2 C102.2 C103.2 C104.2 C105.2 C106.2 C107.2 C108.2 C109.2 C114.2 C115.2 C116.2 C117.2 C118.2 C119.2 C120.2 C121.2 C122.2 C123.2 C128.2 C129.1 C131.2 C132.2 C133.2 C134.2 C136.2 C138.2 C139.2 C162.1 C163.1 C164.1 C165.1 C166.1 C167.1 C168.1 C171.2 C172.2 C301.2 D4.2 D11.2 D14.2 D18.2 D19.2 D20.2 D38.2 D42.2 D45.1 D46.1 J2.1 J2.20 J3.5 J3.6 J6.2 J12.3 J12.5 J12.7 J12.9 LED1.1 LED1.2 LED1.3 Q38.2 Q42.2 Q68.2 R2.1 R13.1 R21.2 R34.1 R199.2 R233.1 R234.1 R247.1 R248.2 R250.1 R252.1 R260.1 R297.1 R325.1 R328.1 R330.2 RT1.1 RT21.1 RT22.1 RT23.1 RT24.1 RT25.1 RT26.1 RT27.1 RT28.1 RT29.1 RT30.1 RT31.1 RT32.1 RT33.1 RT34.1 RT35.1 RT36.1 RT37.1 S1.1 TP4.1 U1.2 U1.8 U2.2 U4.2 U4.8 U6.2 U6.8 U8.2 U8.8 U9.4 U11.17 U17.7 U18.3 U19.4 U19.7 U19.8 U19.11 U20.4 U20.7 U20.8 U20.11 U21.4 U21.7 U21.8 U21.11 U22.3 U22.4 U22.5 U22.6 U23.4 U23.5 U23.6 U23.7 U23.8 U24.1 U24.9@2779.61,1860.41 U25.2 U31.41 Y2.2 Y2.4 | length 137.9
  Top Layer w10: R21.2@1673.42,1474.47 1702.62,1503.66 U31.41@1702.62,1594.69 ; C131.2@3122.23,2143.05 C131.2@3126.2,2147.02
  other v1: 1063.24,925.88 1156.42,941.17 2458.21,1240.35 2528.94,1241.17 2596.62,1242.4 1023.92,1266.77 1023.92,1316.93 2718.54,1345.51 1023.92,1361.19 1640.28,1482.41 2899.71,1496.04 3111.81,1519.03 3203.5,1557.14 1500.2,1584.11 1938.83,1606.33 3206.22,1641.18 3371.59,1671.4 3329.21,1701.63 3373.72,1701.63 3329.21,1735.24 3373.72,1735.24 3412.54,1735.24 3328.11,1774.08 3372.62,1774.08 3411.44,1774.08 2757.96,1783.63 2801.26,1783.63 3327.97,1808.44 3372.48,1808.44 3411.3,1808.44 1788.15,1825.41 1825.09,1825.41 2757.96,1834.82 2801.26,1834.82 1654.94,1869.07 2757.96,1886 2801.26,1886 2757.96,1937.18 2801.26,1937.18 1215.77,1986.58 1251.53,1987.44 1816.34,1987.44 1215.77,2020.7 1251.53,2020.7 2978.59,2144.58 3085.62,2145.41 2037.4,2202.85 1151.21,2216.33 2037.4,2236.2 3410.32,2243.69 1083.12,2298.12 3472.81,2329.12 1930.22,2376.23 3523.48,2381.98 3452.09,2383.39 2273.93,2409.17 1930.75,2426.79 2949.83,2427.17 2996.73,2427.17 3037.86,2427.17 1955.63,2450.36 2316.61,2456.8 3523.62,2472.44 3452.09,2474.41 3124.73,2483.43 2135.75,2507.95 2567.31,2507.95 2611.89,2507.95 3519.03,2551.29 2417.93,2552.39 2443.81,2552.39 3426.6,2552.39 2176.85,2561.87 2043.92,2592.51 3496.67,2635.33 2043.11,2637.6 1095.26,2647.18 1135.35,2647.18 1175.44,2647.18 1215.52,2647.18 1096.42,2678 1136.5,2678 1176.59,2678 1216.68,2678 1256.77,2678 2043.92,2683.82 1488.73,2685.07 2129.03,2685.07 1420.08,2686.17 1057.48,2708.81 1097.57,2708.81 1137.66,2708.81 1177.75,2708.81 1217.84,2708.81 1257.92,2708.81 1298.01,2708.81 1058.64,2739.63 1098.73,2739.63 1138.82,2739.63 1178.9,2739.63 1218.99,2739.63 1259.08,2739.63 1299.17,2739.63 1059.79,2770.44 1099.88,2770.44 1139.97,2770.44 1180.06,2770.44 1220.15,2770.44 1260.23,2770.44 1300.32,2770.44 3540.55,2792.99 3563.99,2793.47 3587.29,2793.47 3611.56,2793.47 1060.95,2801.26 1101.04,2801.26 1141.13,2801.26 1181.21,2801.26 1221.3,2801.26 1261.39,2801.26 1301.48,2801.26 2828.93,2804.87 1062.11,2832.07 1102.19,2832.07 1142.28,2832.07 1182.37,2832.07 1222.46,2832.07 1262.55,2832.07 1302.63,2832.07 2865.03,2838.77 1532.57,2854.26 1063.26,2862.89 1103.35,2862.89 1143.44,2862.89 1183.53,2862.89 1223.61,2862.89 1263.7,2862.89 1303.79,2862.89 2891.75,2868.1 2698.3,2881.69 2742.43,2882.36 2642.94,2883.31 1665.56,2891.24 1064.42,2893.7 1104.5,2893.7 1144.59,2893.7 1184.68,2893.7 1224.77,2893.7 1264.86,2893.7 1304.94,2893.7 1495.95,2893.7 1532.89,2893.7 1571.16,2893.7 2941.24,2944.59 2986.06,2944.59 1603.89,2948.66 1566.87,2989.74 2834.73,3068.45 2964.59,3070.08 2056.64,3077.42 2133.77,3080.02 3426.6,3150.39 3425.2,3208.21 3425.2,3265.14 3425.2,3322.07 3425.2,3378.99 3425.2,3435.92
GND_EXT: C153.2 C155.2 J9.1 U29.12 U29.13 U29.14 U29.15 U29.16 | length 378.1
  Bottom Layer w50: J9.1@1029.42,-759.47 v1(1029.42,-381.36)
  other v1: 1096.68,-382.4 1206.25,-382.4 1267.58,-355.77 1320.82,-355.77 1374.07,-355.77 1427.32,-355.77 1267.58,-288.55 1320.82,-288.55 1374.07,-288.55 1427.32,-288.55 1267.58,-221.32 1320.82,-221.32 1374.07,-221.32 1427.32,-221.32 1214.33,-154.1 1267.58,-154.1 1320.82,-154.1 1374.07,-154.1 1427.32,-154.1 1021.97,-101.57 1058.47,-101.57 1093.52,-101.57 1128.57,-101.57 1167.53,-101.57 1214.33,-86.87 1267.58,-86.87 1320.82,-86.87 1374.07,-86.87 1427.32,-86.87 1021.97,-56.15 1058.47,-56.15 1093.52,-56.15 1128.57,-56.15 1167.53,-56.15
GND_SYS: C4.2 C5.2 C17.2 C18.2 C20.1 C61.2 C62.2 C125.2 C127.2 C130.2 C135.2 C140.1 C148.1 D52.1 D53.1 D54.1 D55.1 D56.1 D57.1 J4.2 J4.4 J4.6 J8.2 J8.4 R52.1 U1.9 U1.10 U1.15 U3.3 U4.9 U4.10 U4.15 U5.3 U6.9 U6.15 U7.3 U8.9 U8.15 U23.12 U23.13 U23.14 U23.15 U23.16 U26.2 U32.1 U33.1 U34.1 | length 52
  Top Layer w10: v1(148.53,1596.71) 148.93,1597.1 194.6,1597.1 U3.3@194.99,1597.49
  Bottom Layer w10: C148.1@478.39,2118.3 C148.1@481.28,2115.41 ; C140.1@480.2,1593.56 C140.1@480.98,1594.34
  other v1: 182.95,2128.99 34.53,2340.5 91.91,2340.5 149.29,2340.5 206.67,2340.5 264.06,2340.5 316.44,2340.5 431.2,2340.5 488.58,2340.5 545.97,2340.5 603.35,2340.5 34.53,2393.75 91.91,2393.75 149.29,2393.75 206.67,2393.75 264.06,2393.75 316.44,2393.75 431.2,2393.75 488.58,2393.75 545.97,2393.75 603.35,2393.75 34.53,2447 91.91,2447 149.29,2447 206.67,2447 264.06,2447 431.2,2447 488.58,2447 545.97,2447 603.35,2447 34.53,2500.25 91.91,2500.25 149.29,2500.25 206.67,2500.25 264.06,2500.25 34.53,2553.5 91.91,2553.5 149.29,2553.5 206.67,2553.5 264.06,2553.5 34.53,2606.74 91.91,2606.74 149.29,2606.74 206.67,2606.74 264.06,2606.74 34.53,2659.99 91.91,2659.99 149.29,2659.99 206.67,2659.99 264.06,2659.99 34.53,2713.24 91.91,2713.24 149.29,2713.24 206.67,2713.24 264.06,2713.24 321.44,2713.24 378.82,2713.24 436.2,2713.24 493.58,2713.24 550.97,2713.24 608.35,2713.24 34.53,2766.49 91.91,2766.49 149.29,2766.49 206.67,2766.49 264.06,2766.49 321.44,2766.49 378.82,2766.49 436.2,2766.49 493.58,2766.49 550.97,2766.49 608.35,2766.49 34.53,2819.74 91.91,2819.74 149.29,2819.74 206.67,2819.74 264.06,2819.74 321.44,2819.74 378.82,2819.74 436.2,2819.74 493.58,2819.74 550.97,2819.74 608.35,2819.74
GND_SYS_EXT: C7.2 C11.2 C141.2 C142.2 C143.2 C144.2 C145.2 C146.2 C147.2 C149.2 C156.2 C157.2 C158.2 J5.2 J11.2 J11.4 R319.1 R326.1 U27.2 U28.4 U28.5 U28.6 U28.7 U28.8 U29.4 U29.5 U29.6 U29.7 U29.8 U30.4
  other v1: 40.25,-965.07 93.5,-965.07 146.74,-965.07 199.99,-965.07 253.24,-965.07 306.49,-965.07 359.74,-965.07 412.98,-965.07 466.23,-965.07 519.48,-965.07 572.73,-965.07 625.98,-965.07 40.25,-907.69 93.5,-907.69 146.74,-907.69 199.99,-907.69 253.24,-907.69 306.49,-907.69 359.74,-907.69 412.98,-907.69 466.23,-907.69 519.48,-907.69 572.73,-907.69 625.98,-907.69 40.25,-850.31 93.5,-850.31 146.74,-850.31 199.99,-850.31 253.24,-850.31 306.49,-850.31 359.74,-850.31 412.98,-850.31 466.23,-850.31 519.48,-850.31 572.73,-850.31 625.98,-850.31 40.25,-792.93 93.5,-792.93 146.74,-792.93 199.99,-792.93 40.25,-735.55 93.5,-735.55 40.25,-678.16 93.5,-678.16 40.25,-620.78 93.5,-620.78 93.5,-576.4 40.25,-563.4 40.25,-506.02 93.5,-506.02 40.25,-448.64 93.5,-448.64 40.25,-391.25 93.5,-391.25 418.8,-382.4 442.22,-382.4 465.64,-382.4 489.06,-382.4 512.48,-382.4 535.9,-382.4 559.32,-382.4 582.74,-382.4 419.69,-344.49 443.11,-344.49 466.53,-344.49 489.95,-344.49 513.37,-344.49 536.79,-344.49 560.21,-344.49 583.64,-344.49 40.25,-333.87 93.5,-333.87 40.25,-276.49 93.5,-276.49 40.25,-219.11 93.5,-219.11 40.25,-161.73 69.63,-161.05 93.5,-161.73 377.13,-117.6 403.75,-117.6 430.37,-117.6 40.25,-104.34 93.5,-104.34 151.88,-86.87 178.5,-86.87 205.13,-86.87 235.05,-86.87 265.76,-86.87 295.87,-86.87 323.89,-86.87 350.52,-86.87 377.14,-86.87 403.76,-86.87 430.39,-86.87 457.01,-86.87 616.76,-86.87 643.38,-86.87 151.89,-56.15 178.52,-56.15 205.14,-56.15 235.06,-56.15 265.77,-56.15 295.89,-56.15 323.91,-56.15 350.53,-56.15 377.15,-56.15 403.78,-56.15 430.4,-56.15 457.03,-56.15 483.65,-56.15 510.27,-56.15 536.9,-56.15 563.52,-56.15 590.15,-56.15 617.15,-56.15 644.15,-56.15
ISO_EN1: U8.7 U31.16 | length 1940
  Top Layer w10: U8.7@1019.56,668.59 v1(1136.57,668.28) ; v1(1388.39,2082.35) 1529.93,2082.35 1544.23,2068.04 1544.23,2044.42 U31.16@1545.14,2043.51
  Bottom Layer w10: v1(1136.57,668.28) 1134.72,670.14 1134.72,676.98 1133.57,678.13 1133.57,2024.56 1191.36,2082.35 v1(1388.39,2082.35)
LED1: R23.1 U31.48 | length 192.3
  Top Layer w10: U31.48@1840.41,1594.69 1840.41,1571.07 1856.09,1555.4 R23.1@2002.56,1555.4
LED2: R24.1 U31.50 | length 139.2
  Top Layer w10: U31.50@1917.19,1691.15 1917.96,1690.37 1950.96,1690.37 1970.26,1671.07 1970.26,1638.08 2001.37,1606.97 R24.1@2002.24,1606.97
LED3: R25.1 U31.51 | length 121.7
  Top Layer w10: U31.51@1917.19,1710.83 1971.29,1710.83 1991.81,1690.32 1991.81,1665.31 1998.62,1658.5 R25.1@2002.56,1658.5
nCS: U31.58
NetD10_1: D10.1 R47.1 | length 78.1
  Top Layer w10: R47.1@5655.5,2616.93 5657.14,2615.29 D10.1@5732.96,2615.29
NetR5_1: R5.1 J12.2 U2.3 | length 416
  Top Layer w10: J12.2@1337.2,2317.61 v1(1409.57,2317.61) 1448.71,2278.47 1522.68,2278.47 R5.1@1580.52,2220.63
  Bottom Layer w10: v1(1409.57,2317.61) 1412.19,2317.61 1426.11,2331.54 1426.78,2331.54 1472.95,2377.71 U2.3@1472.95,2421.96
NetC12_2: C12.2 U31.32 | length 84.5
  Top Layer w10: C12.2@1398.12,1638.46 1398.12,1639.45 1411.82,1653.15 1412.81,1653.15 1431.12,1671.46 U31.32@1468.37,1671.46
NetC13_1: C13.1 R263.2 | length 118.6
  Top Layer w10: R263.2@3040.14,1878.64 3075.17,1878.64 3114.39,1917.86 C13.1@3114.39,1945.98
NetC13_2: C13.2 L10.1 R317.2 R320.1 U24.8
NetC22_2: C22.2 R191.2 U10.23 | length 232
  Top Layer w10: C22.2@4821.61,2435.07 4839.01,2435.07 4891.89,2487.95 U10.23@5031.67,2487.95
NetC23_1: C23.1 R13.2 U31.17 | length 196.8
  Top Layer w10: U31.17@1468.37,1966.74 v1(1524.63,1966.74)
  Bottom Layer w10: R13.2@1398.65,1931.72 1464.59,1931.72 1479.27,1946.4 1480.26,1946.4 1499.79,1965.93 1523.82,1965.93 v1(1524.63,1966.74)
NetC23_2: C23.2 C24.1 U31.24 | length 230.5
  Top Layer w10: v1(1362.41,1826.2) 1365.03,1826.2 1367.77,1828.94 U31.24@1468.37,1828.94
  Bottom Layer w10: v1@1364.26,1828.05 1364.26,1835.33 1397.66,1868.72 C24.1@1398.65,1868.72 C23.2@1465.57,1868.72 C23.2@1465.57,1867.74
NetC27_1: C27.1 C132.1 C133.1 C134.1 L10.2 R264.1 R324.2 | length 827.5
  Top Layer w10: L10.2@2890.83,2255.87 2944.51,2202.19 3157.99,2202.19 3188.62,2171.56 3188.62,1941.18 3076.38,1828.94 3042.45,1828.94 3036.59,1823.08 R324.2@3036.59,1759.61
NetC27_2: C27.2 C112.1 R320.2 | length 1062.4
  Top Layer w10: C27.2@2713.67,2219.57 R320.2@2713.67,2160.44 2713.67,2164.38 2720.48,2171.19 2724.41,2171.19 2732.94,2179.71 3150.29,2179.71 3170.62,2159.37 3170.62,1948.63 3068.93,1846.94 2992.68,1846.94 2969.89,1824.16 C112.1@2969.89,1759.61
NetC56_2: C56.2 R207.1 R208.1 U10.32 | length 204.9
  Top Layer w10: v1@5227.1,2351.18 v1(5227.54,2351.62) U10.32@5227.54,2410.2
  Bottom Layer w10: C56.2@5260.04,2361.02 5250.63,2351.62 v1(5227.54,2351.62) 5227.54,2311.35 R208.1@5231.34,2307.56 5231.83,2307.06 R207.1@5294.83,2307.06
NetC69_1: C69.1 Q34.3 U10.36 | length 686.9
  Top Layer w10: U10.36@5306.28,2410.2 5306.28,2387.56 5322.03,2371.81 v1(5336.9,2371.81)
  Bottom Layer w10: v1(5336.9,2371.81) 5336.9,2442 5379,2484.1 5527.43,2484.1 5527.85,2483.67 5626.26,2483.67 ; C69.1@5491.16,2392.52 5491.16,2393.5 5533.28,2435.63 5578.22,2435.63 5626.26,2483.67 ; Q34.3@5642.23,2553.53 5642.23,2499.64 5626.26,2483.67
NetC79_1: C79.1 Q35.3 U11.36 | length 496.6
  Top Layer w10: U11.36@2235.9,2422.69 2235.9,2400.54 2249.23,2387.22 2255.68,2387.22 2256.57,2386.33 2319.82,2386.33 v1@2332.36,2398.87
  Bottom Layer w10: v1(2332.36,2399.15) 2332.36,2401.77 2340.11,2409.52 2340.11,2459.36 2339.42,2460.06 2339.42,2478.98 2340.11,2479.68 2340.11,2487.98 2362.26,2510.13 2441.9,2510.13 2497.16,2454.87 C79.1@2497.16,2453.88 2504.7,2461.42 Q35.3@2578.21,2461.42
NetC82_1: C82.1 Q34.2 Q34.4 R209.1 | length 531.3
  Bottom Layer w20: R209.1@5728.49,2893.07 5728.49,2786.17 Q34.4@5732.79,2781.88 ; Q34.2@5732.79,2553.53 Q34.4@5732.79,2781.88 ; C82.1@5909.13,2800.04 C82.1@5909.13,2790.2 5908.74,2790.58 5741.49,2790.58 Q34.4@5732.79,2781.88
NetC83_1: C83.1 Q35.2 Q35.4 R213.1 R214.1 | length 642.7
  Bottom Layer w20: Q35.2@2578.21,2370.87 Q35.4@2806.55,2370.87 ; R213.1@2702.22,2559.84 R214.1@2810.49,2559.84 2806.55,2555.91 Q35.4@2806.55,2370.87 ; C83.1@2918.76,2378.74 2814.43,2378.74 Q35.4@2806.55,2370.87
NetC110_1: C110.1 C111.2 | length 838.6
  Bottom Layer w20: C111.2@7217.17,715.09 C110.1@7217.17,1553.7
